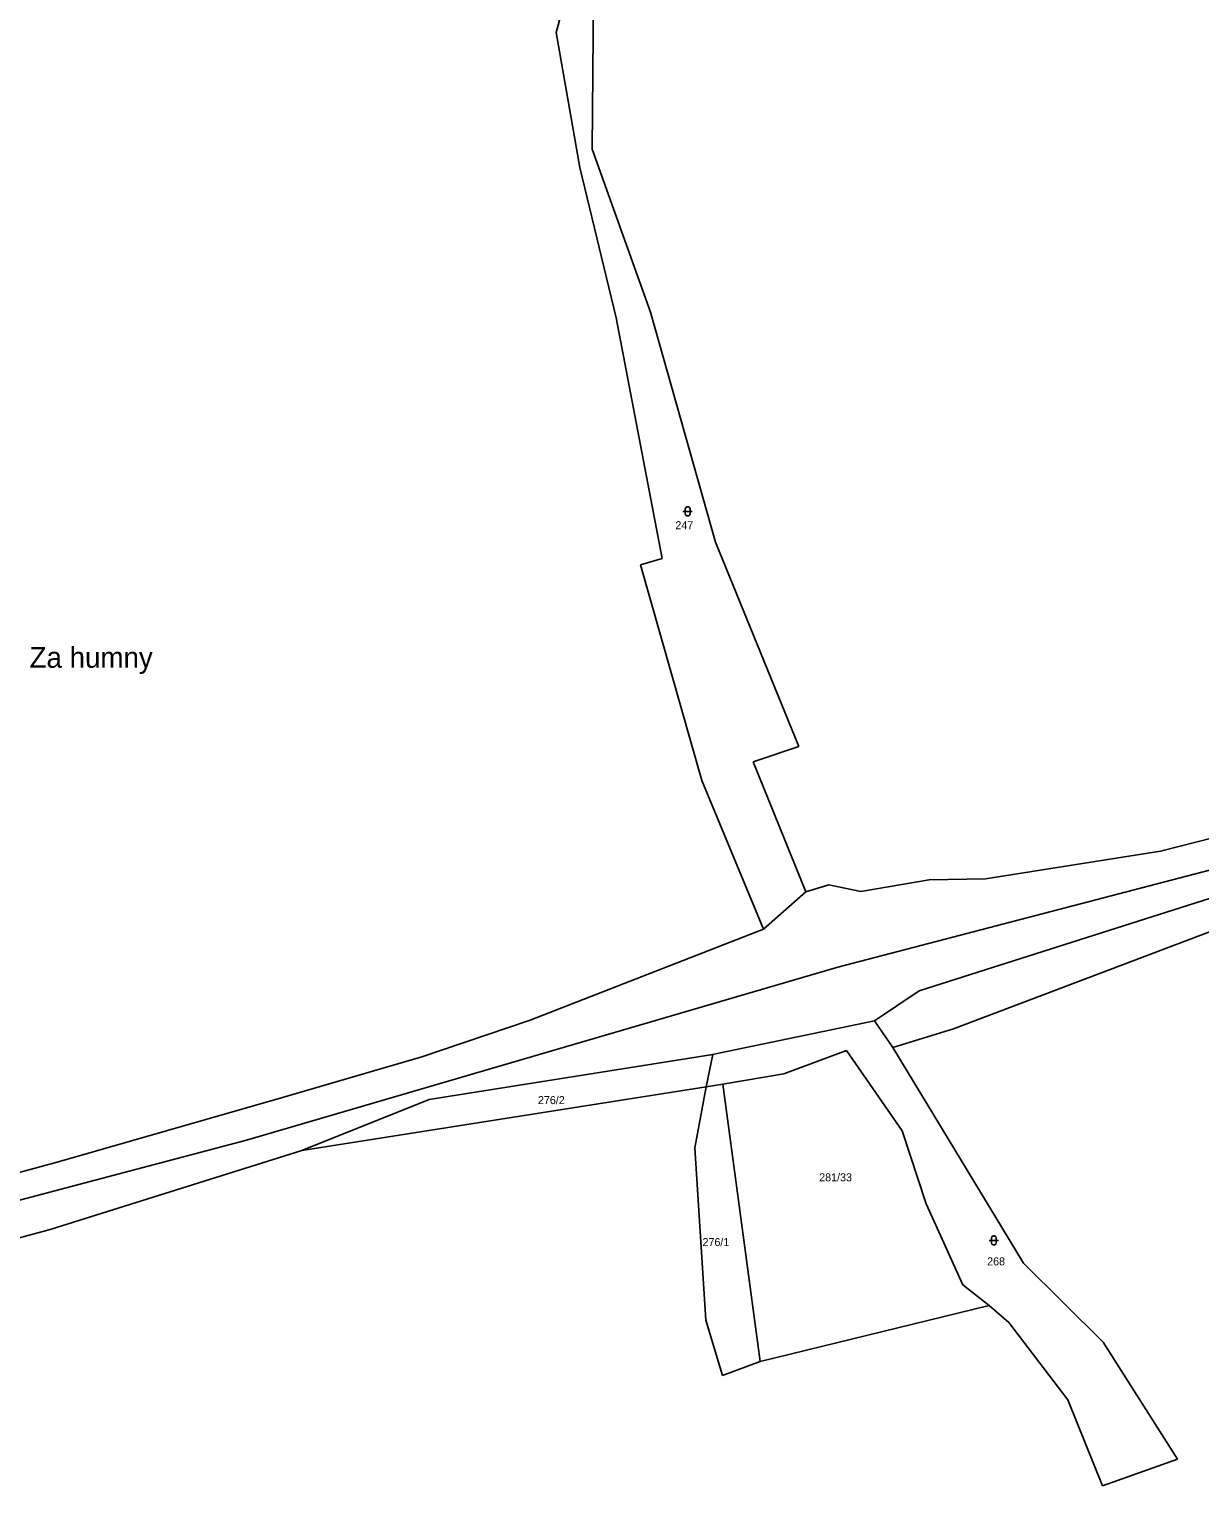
# Model space of a CAD drawing. Extents: x -779723 to -777378, y -1011169 to -1009297.
# Drawn here: x -778656.8 to -778408.1, y -1010420 to -1010110.5 of the extents above; entities that cross this region are included whole.
import ezdxf

# ---------------------------------------------------------------- set-up
doc = ezdxf.new("R2010")
doc.units = 0
for name, color, linetype in [('Default', 7, 'Continuous'), ('KN_HRANICE', 7, 'Continuous'), ('KN_KULTURY', 7, 'Continuous'), ('KN_PARCELY', 7, 'Continuous'), ('KN_VEDENI', 7, 'Continuous')]:
    doc.layers.add(name, color=color, linetype=linetype)

# ---------------------------------------------------------------- blocks, each defined once
blk = doc.blocks.new('316')
at = {"layer": 'Default'}
for points in [[(-1, 1), (0.27, 1), (1, 1)], [(-0.5, 1.5), (-0.4, 1.79), (-0.15, 1.97), (0.16, 1.97), (0.41, 1.79), (0.51, 1.5), (0.51, 0.5), (0.41, 0.21), (0.16, 0.03), (-0.15, 0.03), (-0.4, 0.21), (-0.5, 0.5), (-0.5, 1.5)]]:
    blk.add_lwpolyline(points, dxfattribs=at)

msp = doc.modelspace()

# ---------------------------------------------------------------- linework, layer by layer
at = {"layer": 'KN_HRANICE'}
for p, q in [((-778541.98, -1010100.57), (-778544.84, -1010111.19)), ((-778536.83, -1010100.87), (-778537.2, -1010135.97)), ((-778544.84, -1010111.19), (-778539.76, -1010139.89)), ((-778537.2, -1010135.97), (-778524.77, -1010170.64)), ((-778539.76, -1010139.89), (-778532.06, -1010171.83)), ((-778532.06, -1010171.83), (-778522.27, -1010222.95)), ((-778524.77, -1010170.64), (-778510.96, -1010219.51)), ((-778510.96, -1010219.51), (-778493.25, -1010262.91)), ((-778522.27, -1010222.95), (-778526.89, -1010224.31)), ((-778526.89, -1010224.31), (-778513.85, -1010270.13)), ((-778502.97, -1010266.15), (-778493.25, -1010262.91)), ((-778502.97, -1010266.15), (-778491.82, -1010293.76)), ((-778513.85, -1010270.13), (-778500.81, -1010301.69)), ((-778416.45, -1010285.13), (-778355.22, -1010269.42)), ((-778467.71, -1010314.76), (-778368.39, -1010283.19)), ((-778453.63, -1010290.98), (-778416.45, -1010285.13)), ((-778491.82, -1010293.76), (-778486.94, -1010292.24)), ((-778480.1, -1010293.71), (-778486.94, -1010292.24)), ((-778480.1, -1010293.71), (-778465.61, -1010291.22)), ((-778465.61, -1010291.22), (-778453.63, -1010290.98)), ((-778500.81, -1010301.69), (-778491.82, -1010293.76)), ((-778500.81, -1010301.69), (-778550.31, -1010321.04)), ((-778460.45, -1010322.86), (-778400.28, -1010300.05)), ((-778477.19, -1010321.19), (-778467.71, -1010314.76)), ((-778550.31, -1010321.04), (-778573.36, -1010328.79)), ((-778510.29, -1010328.03), (-778477.19, -1010321.19)), ((-778477.19, -1010321.19), (-778473.29, -1010326.85)), ((-778473.29, -1010326.85), (-778460.45, -1010322.86)), ((-778473.29, -1010326.85), (-778445.56, -1010372.62)), ((-778573.36, -1010328.79), (-778603.44, -1010337.58)), ((-778571.77, -1010337.89), (-778511.55, -1010328.28)), ((-778511.55, -1010328.28), (-778512.93, -1010335.18)), ((-778511.55, -1010328.28), (-778510.29, -1010328.03)), ((-778483.13, -1010327.49), (-778496.48, -1010332.41)), ((-778483.13, -1010327.49), (-778471.36, -1010344.5)), ((-778509.43, -1010334.65), (-778496.48, -1010332.41)), ((-778598.81, -1010348.7), (-778512.93, -1010335.18)), ((-778512.93, -1010335.18), (-778515.35, -1010348.17)), ((-778512.93, -1010335.18), (-778509.43, -1010334.65)), ((-778501.51, -1010393.56), (-778509.43, -1010334.65)), ((-778603.44, -1010337.58), (-778650.77, -1010351.2)), ((-778571.77, -1010337.89), (-778598.81, -1010348.7)), ((-778471.36, -1010344.5), (-778466.21, -1010360.03)), ((-778652.28, -1010365.5), (-778598.81, -1010348.7)), ((-778515.35, -1010348.17), (-778513.04, -1010384.74)), ((-778650.77, -1010351.2), (-778703.98, -1010365.37)), ((-778466.21, -1010360.03), (-778458.48, -1010377.24)), ((-778678, -1010372.43), (-778652.28, -1010365.5)), ((-778445.56, -1010372.62), (-778428.61, -1010389.44)), ((-778458.48, -1010377.24), (-778452.86, -1010381.6)), ((-778501.51, -1010393.56), (-778452.86, -1010381.6)), ((-778452.86, -1010381.6), (-778448.7, -1010385.27)), ((-778513.04, -1010384.74), (-778509.52, -1010396.54)), ((-778448.7, -1010385.27), (-778436.16, -1010401.64)), ((-778428.61, -1010389.44), (-778412.85, -1010414.3)), ((-778509.52, -1010396.54), (-778501.51, -1010393.56)), ((-778428.76, -1010419.95), (-778436.16, -1010401.64)), ((-778428.76, -1010419.95), (-778412.85, -1010414.3))]:
    msp.add_line(p, q, dxfattribs=at)
at = {"layer": 'KN_VEDENI'}
for p, q in [((-778485, -1010309.77), (-778348.82, -1010274.15)), ((-778610.59, -1010346.52), (-778485, -1010309.77)), ((-778682.94, -1010365.64), (-778610.59, -1010346.52))]:
    msp.add_line(p, q, dxfattribs=at)

# ---------------------------------------------------------------- block references
at = {"layer": 'KN_KULTURY'}
for p in [(-778516.9, -1010213.94), (-778451.87, -1010368.81)]:
    msp.add_blockref('316', p, dxfattribs=at)

# ---------------------------------------------------------------- texts
at = {"layer": 'KN_PARCELY'}
for s, height, p in [('247', 1.7, (-778519.5, -1010216.72)), ('Za humny', 4.4, (-778656.66, -1010246.16)), ('276/2', 1.7, (-778548.69, -1010338.85)), ('281/33', 1.7, (-778488.95, -1010355.25)), ('276/1', 1.7, (-778513.73, -1010369.01)), ('268', 1.7, (-778453.28, -1010373.11))]:
    msp.add_text(s, height=height, dxfattribs=at).set_placement(p)

doc.saveas('drawing.dxf')
